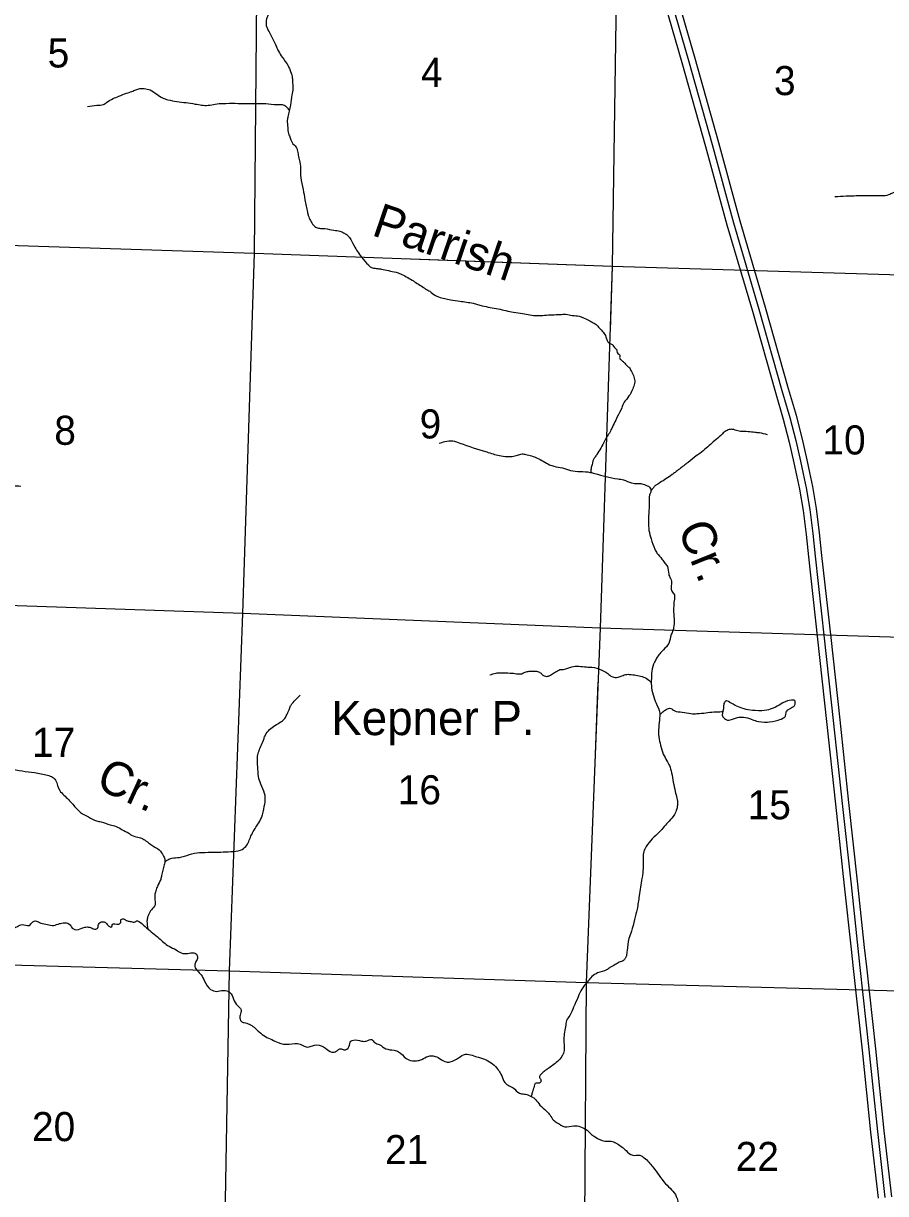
# Model space of a CAD drawing. Extents: x 1219626 to 1426462, y 456797 to 752399.
# Drawn here: x 1317145 to 1329747, y 576968 to 594067 of the extents above; entities that cross this region are included whole.
import ezdxf

# ---------------------------------------------------------------- set-up
doc = ezdxf.new("R2010")
doc.units = 0
for name, color, linetype in [('Lakes and Ponds', 7, 'Continuous'), ('Masks', 7, 'Continuous'), ('Narrow River Creek and Branch and Slough', 7, 'Continuous'), ('Narrow River Creek and Branch and Slough Text', 7, 'Continuous'), ('Section Lines', 7, 'Continuous'), ('Section Numbers', 7, 'Continuous'), ('State Route Divided Highway Outline and Fill', 7, 'Continuous'), ('State Routes Highway Center Lines', 7, 'Continuous')]:
    doc.layers.add(name, color=color, linetype=linetype)

msp = doc.modelspace()

# ---------------------------------------------------------------- linework, layer by layer
at = {"layer": 'Lakes and Ponds'}
msp.add_lwpolyline([(1327357, 583958), (1327369, 583936), (1327380, 583921), (1327390, 583911), (1327405, 583899), (1327414, 583894), (1327423, 583890), (1327435, 583887), (1327457, 583886), (1327477, 583889), (1327494, 583893), (1327554, 583915), (1327584, 583924), (1327600, 583927), (1327615, 583928), (1327671, 583928), (1327699, 583926), (1327726, 583921), (1327744, 583917), (1327773, 583906), (1327816, 583887), (1327838, 583879), (1327860, 583872), (1327890, 583866), (1327934, 583859), (1327978, 583857), (1328019, 583858), (1328049, 583861), (1328094, 583868), (1328139, 583877), (1328174, 583885), (1328200, 583893), (1328219, 583900), (1328246, 583914), (1328273, 583930), (1328281, 583939), (1328285, 583948), (1328288, 583966), (1328291, 583996), (1328294, 584009), (1328297, 584015), (1328302, 584019), (1328320, 584035), (1328350, 584056), (1328380, 584075), (1328393, 584081), (1328405, 584087), (1328410, 584090), (1328417, 584100), (1328421, 584110), (1328424, 584121), (1328426, 584140), (1328425, 584154), (1328423, 584163), (1328420, 584169), (1328415, 584175), (1328408, 584179), (1328389, 584180), (1328371, 584179), (1328339, 584174), (1328314, 584167), (1328278, 584154), (1328244, 584138), (1328190, 584106), (1328163, 584090), (1328135, 584075), (1328105, 584062), (1328059, 584045), (1328036, 584038), (1328012, 584033), (1327970, 584027), (1327938, 584024), (1327890, 584024), (1327842, 584026), (1327801, 584029), (1327740, 584037), (1327710, 584043), (1327680, 584051), (1327645, 584062), (1327596, 584081), (1327548, 584102), (1327517, 584118), (1327472, 584145), (1327450, 584158), (1327427, 584167), (1327422, 584167), (1327413, 584165), (1327407, 584161), (1327397, 584153), (1327390, 584142), (1327383, 584129), (1327380, 584117), (1327377, 584096), (1327377, 584066), (1327376, 584050), (1327374, 584035), (1327365, 583995), (1327357, 583958)], dxfattribs=at)
at = {"layer": 'Masks'}
for p, q in [((1322815, 590628), (1325752, 590522)), ((1325752, 590522), (1325720, 589579)), ((1325543, 584442), (1325497, 583255))]:
    msp.add_line(p, q, dxfattribs=at)
at = {"layer": 'Narrow River Creek and Branch and Slough'}
for points in [[(1318897, 596656), (1318950, 596650), (1319024, 596629), (1319102, 596597), (1319241, 596529), (1319370, 596468), (1319474, 596402), (1319520, 596371), (1319632, 596282), (1319700, 596227), (1319763, 596193), (1319842, 596157), (1319905, 596115), (1319943, 596077), (1320034, 595971), (1320085, 595912), (1320106, 595865), (1320148, 595745), (1320176, 595686), (1320205, 595618), (1320243, 595548), (1320303, 595421), (1320326, 595393), (1320421, 595351), (1320535, 595317), (1320590, 595317), (1320757, 595345), (1320854, 595351), (1320912, 595343), (1320977, 595328), (1321024, 595298), (1321123, 595237), (1321163, 595207), (1321188, 595110), (1321186, 595011), (1321188, 594939), (1321163, 594865), (1321131, 594759), (1321089, 594649), (1321072, 594605), (1321007, 594514), (1320886, 594383), (1320808, 594300), (1320755, 594243), (1320730, 594204), (1320707, 594156), (1320692, 594065), (1320702, 594010), (1320747, 593923), (1320785, 593847), (1320842, 593727), (1320874, 593659), (1320926, 593574), (1321013, 593449), (1321038, 593392), (1321074, 593286), (1321076, 593231), (1321083, 593157), (1321085, 593113), (1321070, 593022), (1321047, 592874), (1321028, 592785), (1321011, 592703), (1321002, 592652), (1321009, 592546), (1321011, 592500), (1321032, 592422), (1321055, 592364), (1321072, 592326), (1321129, 592261), (1321148, 592218), (1321163, 592142), (1321182, 592058), (1321186, 592041), (1321195, 591916), (1321199, 591815), (1321233, 591641), (1321258, 591489), (1321296, 591309), (1321309, 591260), (1321385, 591119), (1321429, 591085), (1321486, 591072), (1321552, 591068), (1321683, 591045), (1321770, 591030), (1321823, 591009), (1321875, 590977), (1321910, 590939), (1321977, 590818), (1322085, 590651)], [(1318080, 592851), (1318219, 592870), (1318314, 592882), (1318365, 592914), (1318457, 592968), (1318539, 593003), (1318653, 593047), (1318729, 593073), (1318790, 593098), (1318847, 593114), (1318910, 593114), (1318999, 593095), (1319094, 593031), (1319180, 592978), (1319256, 592952), (1319389, 592927), (1319655, 592889), (1319845, 592870), (1319950, 592889), (1320061, 592898), (1320419, 592898), (1320727, 592892), (1320892, 592882), (1320929, 592882), (1320979, 592857), (1321011, 592822), (1321030, 592797)], [(1329007, 591538), (1329169, 591545), (1329404, 591552), (1329681, 591552), (1329795, 591566), (1329854, 591593), (1329937, 591607), (1330002, 591607), (1330075, 591552), (1330196, 591441), (1330245, 591379), (1330307, 591320), (1330355, 591303), (1330583, 591334), (1330670, 591341), (1330774, 591372), (1330843, 591400), (1330936, 591400), (1331012, 591400), (1331057, 591386), (1331090, 591376)], [(1322085, 590651), (1322187, 590537), (1322222, 590505), (1322273, 590490), (1322326, 590484), (1322377, 590478), (1322480, 590454), (1322592, 590431), (1322656, 590408), (1322740, 590366), (1322825, 590315), (1322977, 590218), (1323024, 590188), (1323083, 590152), (1323167, 590093), (1323212, 590072), (1323303, 590046), (1323387, 590029), (1323524, 590008), (1323719, 589977), (1323783, 589960), (1323852, 589941), (1324085, 589896), (1324309, 589846), (1324442, 589827), (1324653, 589797), (1324763, 589803), (1324989, 589814), (1325072, 589816), (1325167, 589801), (1325268, 589787), (1325321, 589769), (1325404, 589729), (1325474, 589693), (1325527, 589657), (1325552, 589630), (1325651, 589505), (1325664, 589473), (1325683, 589422), (1325710, 589393), (1325748, 589376), (1325795, 589319), (1325816, 589297), (1325818, 589276), (1325835, 589245), (1325860, 589219), (1325860, 589177), (1325892, 589141), (1325924, 589111), (1325966, 589067), (1326002, 589033), (1326019, 589004), (1326044, 588959), (1326074, 588885), (1326078, 588803), (1326051, 588729), (1326011, 588646), (1325945, 588557), (1325926, 588532), (1325890, 588449), (1325825, 588318), (1325778, 588219), (1325732, 588126), (1325715, 588090), (1325693, 588056), (1325641, 587971), (1325584, 587861), (1325527, 587770), (1325495, 587724), (1325472, 587686), (1325463, 587639), (1325444, 587578), (1325440, 587504)], [(1328019, 588057), (1327903, 588082), (1327836, 588090), (1327736, 588101), (1327628, 588105), (1327550, 588124), (1327506, 588135), (1327444, 588126), (1327387, 588095), (1327337, 588044), (1327246, 587968), (1327168, 587898), (1327079, 587822), (1326979, 587746), (1326859, 587653), (1326732, 587555), (1326671, 587507), (1326626, 587473), (1326536, 587411), (1326453, 587359), (1326407, 587329), (1326371, 587304), (1326341, 587266), (1326315, 587236)], [(1323221, 587932), (1323304, 587957), (1323421, 587967), (1323523, 587935), (1323916, 587805), (1324103, 587751), (1324211, 587738), (1324366, 587757), (1324433, 587776), (1324486, 587770), (1324655, 587716), (1324743, 587668), (1324835, 587618), (1324899, 587595), (1325022, 587573), (1325140, 587535), (1325431, 587507), (1325495, 587491), (1325831, 587411), (1325917, 587397), (1326034, 587352), (1326120, 587343), (1326186, 587340), (1326263, 587311), (1326297, 587292), (1326313, 587219), (1326297, 587175), (1326291, 587067), (1326285, 586911), (1326282, 586737), (1326288, 586658), (1326320, 586534), (1326374, 586385), (1326405, 586328), (1326478, 586239), (1326519, 586182), (1326557, 586131), (1326576, 586020), (1326602, 585956), (1326618, 585918), (1326611, 585830), (1326624, 585772), (1326659, 585715), (1326659, 585652), (1326649, 585468), (1326640, 585201), (1326614, 585135), (1326576, 585008), (1326500, 584913), (1326399, 584792), (1326370, 584735), (1326329, 584599), (1326323, 584488), (1326323, 584392), (1326348, 584256), (1326393, 584132), (1326446, 583990), (1326443, 583920), (1326431, 583780), (1326431, 583640), (1326459, 583520), (1326497, 583390), (1326551, 583292), (1326586, 583222), (1326618, 583117), (1326672, 582841), (1326706, 582654), (1326694, 582590), (1326659, 582505), (1326583, 582410), (1326437, 582251), (1326247, 582038), (1326212, 581966), (1326205, 581794), (1326196, 581645), (1326186, 581572), (1326145, 581321), (1326114, 581125), (1326076, 580972), (1326031, 580801), (1325996, 580693), (1325968, 580519), (1325965, 580481), (1325942, 580405), (1325914, 580373), (1325854, 580347), (1325793, 580313), (1325717, 580271), (1325667, 580236), (1325537, 580192), (1325451, 580138)], [(1317108, 587302), (1316885, 587316), (1316747, 587335), (1316547, 587345), (1316300, 587335), (1316153, 587316), (1316072, 587307), (1316010, 587268), (1315943, 587216), (1315877, 587169), (1315796, 587140), (1315720, 587121), (1315515, 587126), (1315434, 587097), (1315349, 587026), (1315292, 586973), (1315273, 586931), (1315235, 586716), (1315225, 586607), (1315216, 586379), (1315220, 586260), (1315187, 586126), (1315173, 585974), (1315197, 585836), (1315239, 585632), (1315301, 585393), (1315339, 585317), (1315449, 585241), (1315553, 585194), (1315615, 585146), (1315720, 585041), (1315810, 584932), (1315829, 584837), (1315848, 584708), (1315862, 584551), (1315858, 584394), (1315858, 584189), (1315896, 584009), (1315934, 583914), (1316015, 583837), (1316133, 583766), (1316276, 583704), (1316357, 583671), (1316419, 583623), (1316614, 583423), (1316756, 583290), (1316837, 583233), (1316947, 583185), (1317308, 583119), (1317498, 583081), (1317570, 583052), (1317613, 583009), (1317676, 582856), (1317738, 582790), (1317866, 582656), (1317981, 582537), (1318095, 582471), (1318214, 582414), (1318280, 582400), (1318413, 582357), (1318499, 582333), (1318589, 582285), (1318684, 582233), (1318727, 582204), (1318818, 582176), (1318889, 582152), (1319022, 582057), (1319127, 581990), (1319193, 581900), (1319212, 581838), (1319203, 581771), (1319165, 581614), (1319151, 581557), (1319103, 581457), (1319079, 581391), (1319065, 581324), (1319070, 581234), (1319070, 581186), (1319017, 581115), (1318975, 581043), (1318960, 581005), (1318951, 580948), (1318964, 580834)], [(1323962, 584546), (1324054, 584574), (1324124, 584577), (1324257, 584574), (1324327, 584568), (1324428, 584565), (1324463, 584580), (1324520, 584599), (1324596, 584603), (1324659, 584596), (1324710, 584571), (1324739, 584542), (1324774, 584527), (1324805, 584527), (1324837, 584536), (1324891, 584574), (1324951, 584606), (1324986, 584625), (1325040, 584628), (1325160, 584666), (1325373, 584663), (1325452, 584660), (1325601, 584615), (1325674, 584577), (1325731, 584530), (1325788, 584511), (1325890, 584533), (1325966, 584555), (1326029, 584552), (1326210, 584514), (1326245, 584498), (1326322, 584435)], [(1319211, 581821), (1319258, 581846), (1319316, 581869), (1319425, 581879), (1319572, 581922), (1319720, 581950), (1319886, 581955), (1320176, 581965), (1320319, 581988), (1320395, 582041), (1320471, 582193), (1320571, 582364), (1320623, 582460), (1320666, 582626), (1320680, 582750), (1320671, 582816), (1320614, 582950), (1320581, 583064), (1320571, 583202), (1320566, 583345), (1320581, 583416), (1320652, 583592), (1320671, 583644), (1320695, 583692), (1320842, 583820), (1320918, 583868), (1320966, 583911), (1320994, 583963), (1321028, 584035), (1321051, 584096), (1321075, 584130), (1321189, 584249)], [(1326449, 583971), (1326493, 584009), (1326538, 584041), (1326607, 584057), (1326658, 584025), (1326772, 584003), (1326902, 583981), (1326988, 583981), (1327121, 583994), (1327238, 584006), (1327352, 584013), (1327370, 584019)], [(1313053, 580900), (1313186, 580848), (1313268, 580811), (1313349, 580774), (1313505, 580774), (1313786, 580863), (1314001, 580929), (1314194, 580974), (1314342, 580996), (1314712, 580974), (1315001, 580959), (1315171, 580989), (1315327, 580959), (1315482, 580907), (1315549, 580959), (1315675, 581018), (1315734, 581018), (1315801, 581011), (1315904, 581033), (1315956, 581003), (1316001, 581003), (1316134, 580959), (1316208, 580877), (1316260, 580833), (1316304, 580803), (1316437, 580818), (1316697, 580870), (1316830, 580877), (1316904, 580833), (1316963, 580840), (1317059, 580870), (1317126, 580900), (1317230, 580885), (1317282, 580937), (1317319, 580952), (1317378, 580929), (1317474, 580907), (1317563, 580885), (1317652, 580907), (1317726, 580922), (1317815, 580907), (1317859, 580848), (1317896, 580826), (1318000, 580848), (1318059, 580863), (1318126, 580855), (1318185, 580833), (1318222, 580840), (1318244, 580900), (1318281, 580937), (1318326, 580937), (1318385, 580885), (1318422, 580863), (1318444, 580885), (1318444, 580900), (1318540, 580907), (1318570, 580937), (1318570, 580966), (1318607, 580981), (1318666, 580952), (1318718, 580944), (1318777, 580937), (1318800, 580952), (1318844, 580937), (1318948, 580848), (1319125, 580700), (1319273, 580581), (1319377, 580529), (1319451, 580485), (1319547, 580477), (1319636, 580485), (1319681, 580455), (1319688, 580403), (1319658, 580344), (1319651, 580285), (1319688, 580225), (1319741, 580166), (1319792, 580070), (1319881, 579951), (1319970, 579922), (1320066, 579937), (1320163, 579907), (1320215, 579811), (1320274, 579714), (1320326, 579655), (1320311, 579574), (1320311, 579514), (1320326, 579485), (1320392, 579462), (1320466, 579433), (1320592, 579329)], [(1325451, 580138), (1325348, 580011), (1325307, 579957), (1325253, 579843), (1325187, 579694), (1325129, 579570), (1325085, 579497), (1325069, 579405), (1325050, 579303), (1325044, 579196), (1325050, 579104), (1325037, 579018), (1325015, 578973), (1324949, 578897), (1324806, 578789), (1324755, 578751), (1324708, 578707), (1324689, 578666), (1324701, 578644), (1324708, 578602), (1324676, 578579), (1324641, 578582), (1324603, 578512), (1324581, 578439), (1324567, 578389)], [(1320592, 579329), (1320681, 579262), (1320777, 579218), (1320866, 579174), (1321029, 579151), (1321192, 579151), (1321303, 579107), (1321370, 579129), (1321496, 579129), (1321562, 579092), (1321651, 579033), (1321718, 579048), (1321784, 579085), (1321829, 579070), (1321903, 579114), (1321932, 579196), (1321969, 579211), (1322088, 579196), (1322155, 579196), (1322236, 579218), (1322280, 579174), (1322347, 579144), (1322443, 579085), (1322562, 579062), (1322628, 579040), (1322740, 578944), (1322777, 578922), (1322888, 578907), (1322969, 578929), (1323058, 578973), (1323162, 578973), (1323250, 578929), (1323324, 578892), (1323384, 578892), (1323502, 578951), (1323606, 579003), (1323702, 578988), (1323798, 578959), (1323909, 578922), (1324080, 578781), (1324124, 578714), (1324169, 578610), (1324228, 578551), (1324302, 578514), (1324398, 578433), (1324450, 578425), (1324517, 578410), (1324628, 578344), (1324694, 578262), (1324791, 578173), (1324842, 578114), (1324894, 578040), (1324946, 578003), (1325057, 577944), (1325190, 577958), (1325287, 577944), (1325383, 577892), (1325450, 577833), (1325501, 577796), (1325642, 577736), (1325687, 577736), (1325753, 577729), (1325894, 577647), (1325953, 577595), (1326050, 577527), (1326154, 577527), (1326220, 577490), (1326346, 577357), (1326531, 577112), (1326687, 576927), (1326724, 576786), (1326761, 576705), (1326865, 576631), (1326902, 576542), (1327013, 576460), (1327065, 576327), (1327139, 576290), (1327235, 576231), (1327287, 576060), (1327279, 575682), (1327287, 575475), (1327264, 575356), (1327220, 575260), (1327190, 575149), (1327227, 575090), (1327220, 575008), (1327153, 574934), (1327124, 574838), (1327168, 574742), (1327250, 574601), (1327287, 574527)]]:
    msp.add_spline(points, degree=3, dxfattribs=at)
at = {"layer": 'Section Lines'}
for p, q in [((1320522, 590711), (1320574, 596075)), ((1325831, 595870), (1325752, 590520)), ((1315217, 590884), (1320522, 590711)), ((1320350, 585446), (1320522, 590711)), ((1320522, 590711), (1325752, 590520)), ((1325752, 590520), (1325573, 585231)), ((1325752, 590520), (1330971, 590364)), ((1320350, 585446), (1315047, 585620)), ((1320155, 580224), (1320350, 585446)), ((1325573, 585231), (1320350, 585446)), ((1325573, 585231), (1325372, 580050)), ((1330814, 585068), (1325573, 585231)), ((1314899, 580368), (1320155, 580224)), ((1320064, 574907), (1320155, 580224)), ((1320155, 580224), (1325372, 580050)), ((1325372, 580050), (1325335, 574748)), ((1325372, 580050), (1330699, 579912))]:
    msp.add_line(p, q, dxfattribs=at)
at = {"layer": 'State Route Divided Highway Outline and Fill'}
for points in [[(1329836, 576922), (1329726, 577886), (1329603, 579083), (1329471, 580281), (1329440, 580562), (1329341, 581487), (1329211, 582681), (1329081, 583890), (1328949, 585093), (1328817, 586294), (1328782, 586623), (1328737, 586979), (1328682, 587299), (1328641, 587505), (1328602, 587690), (1328532, 587994), (1328442, 588336), (1328327, 588729), (1327991, 589918), (1327621, 591179), (1327307, 592324), (1326961, 593553), (1326616, 594750)], [(1326423, 594695), (1326769, 593498), (1327114, 592270), (1327428, 591125), (1327799, 589863), (1328135, 588674), (1328249, 588282), (1328338, 587946), (1328407, 587647), (1328445, 587464), (1328486, 587262), (1328540, 586950), (1328584, 586600), (1328619, 586273), (1328751, 585071), (1328882, 583868), (1329012, 582659), (1329143, 581466), (1329241, 580540), (1329273, 580259), (1329404, 579062), (1329527, 577864), (1329637, 576900)]]:
    msp.add_lwpolyline(points, dxfattribs=at)
at = {"layer": 'State Routes Highway Center Lines'}
msp.add_lwpolyline([(1326519, 594723), (1326865, 593525), (1327210, 592297), (1327525, 591152), (1327895, 589891), (1328231, 588701), (1328345, 588309), (1328435, 587970), (1328505, 587669), (1328543, 587485), (1328584, 587281), (1328638, 586964), (1328683, 586611), (1328718, 586283), (1328850, 585082), (1328982, 583879), (1329112, 582670), (1329242, 581477), (1329341, 580551), (1329372, 580270), (1329504, 579073), (1329626, 577875), (1329737, 576911)], dxfattribs=at)

# ---------------------------------------------------------------- texts
at = {"layer": 'Narrow River Creek and Branch and Slough Text'}
for s, rotation, p in [('Parrish', 341.2151, (1322219, 590977)), ('Cr.', 292.0115, (1326703, 586688)), ('Kepner P.', 0.0002, (1321644, 583667)), ('Cr.', 335.2828, (1318182, 582903))]:
    msp.add_text(s, height=500, rotation=rotation, dxfattribs=at).set_placement(p)
at = {"layer": 'Section Numbers'}
for s, rotation, p in [('5', 0.0001, (1317499, 593423)), ('4', 0.0001, (1322956, 593140)), ('3', 0.0001, (1328115, 593019)), ('9', 0.0001, (1322936, 588002)), ('8', 0.0001, (1317596, 587909)), ('10', 0.0001, (1328823, 587768)), ('17', 0.0002, (1317271, 583349)), ('16', 0.0002, (1322616, 582656)), ('15', 0.0002, (1327730, 582437)), ('20', 0.0002, (1317270, 577734)), ('21', 0.0002, (1322429, 577398)), ('22', 0.0002, (1327555, 577298))]:
    msp.add_text(s, height=425, rotation=rotation, dxfattribs=at).set_placement(p)

doc.saveas('drawing.dxf')
